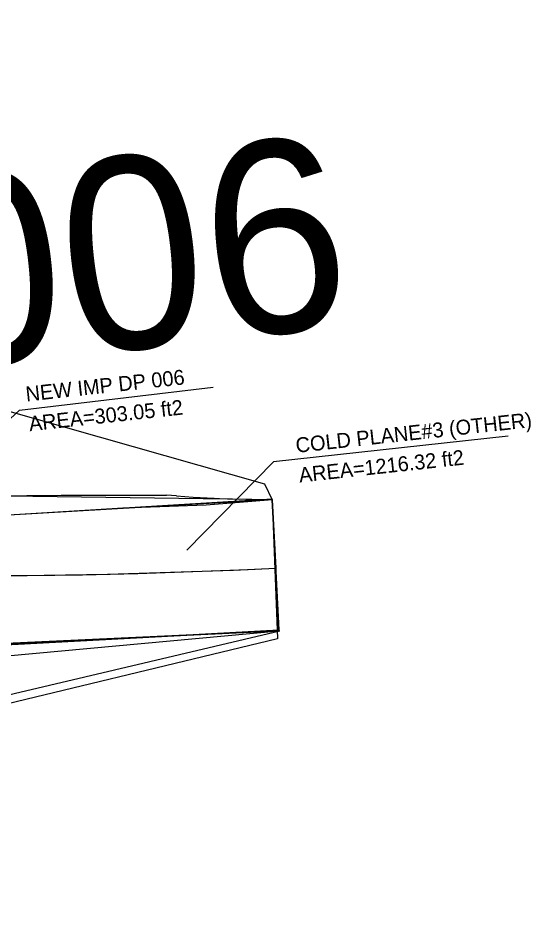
# Model space of a CAD drawing. Extents: x 1509538 to 1510847, y 401283 to 402022.
# Drawn here: x 1510636.5 to 1510732.7, y 401595.5 to 401764.5 of the extents above; entities that cross this region are included whole.
import ezdxf

# ---------------------------------------------------------------- set-up
doc = ezdxf.new("R2010")
doc.units = 0
for name, color, linetype in [('LAWE_P_T', 7, 'Continuous'), ('LDEFAULT_P', 7, 'Continuous'), ('Level 1', 7, 'Continuous'), ('Level 14', 7, 'Continuous'), ('Level 18', 7, 'Continuous'), ('Level 20', 7, 'Continuous'), ('Level 23', 7, 'Continuous'), ('Level 24', 7, 'Continuous'), ('Level 3', 7, 'Continuous'), ('PCH_P', 7, 'Continuous')]:
    doc.layers.add(name, color=color, linetype=linetype)

msp = doc.modelspace()

# ---------------------------------------------------------------- linework, layer by layer
at = {"layer": 'LAWE_P_T'}
for p, q in [((1510728.37, 401686.14), (1510684.4, 401681.34)), ((1510684.4, 401681.34), (1510668.15, 401664.81))]:
    msp.add_line(p, q, dxfattribs=at)
at = {"layer": 'LDEFAULT_P'}
msp.add_lwpolyline([(1510617.08, 401672.79), (1510636.74, 401691.05), (1510673.06, 401695.31)], dxfattribs=at)
at = {"layer": 'Level 1'}
for p, q in [((1510684.29, 401671.55), (1510684.15, 401674.32)), ((1510684.43, 401668.67), (1510684.29, 401671.55)), ((1510684.49, 401667.6), (1510684.43, 401668.67)), ((1510684.57, 401665.85), (1510684.49, 401667.6)), ((1510684.67, 401663.86), (1510684.57, 401665.85)), ((1510684.93, 401658.68), (1510684.67, 401663.86)), ((1510684.86, 401660.03), (1510684.72, 401662.82)), ((1510684.97, 401657.89), (1510684.86, 401660.03)), ((1510685.05, 401656.24), (1510684.93, 401658.68)), ((1510685.05, 401656.24), (1510684.97, 401657.89)), ((1510685.14, 401654.33), (1510685.05, 401656.24)), ((1510685.14, 401654.33), (1510685.05, 401656.24)), ((1510685.24, 401652.41), (1510685.14, 401654.33)), ((1510685.24, 401652.41), (1510685.14, 401654.33)), ((1510685.29, 401651.48), (1510685.24, 401652.41)), ((1510685.29, 401651.48), (1510685.24, 401652.41)), ((1510685.34, 401650.35), (1510685.29, 401651.48)), ((1510634.89, 401647.08), (1510685.37, 401649.83)), ((1510634.89, 401647.3), (1510685.38, 401649.66)), ((1510685.37, 401649.83), (1510685.31, 401650.97)), ((1510685.31, 401650.97), (1510685.31, 401650.97)), ((1510685.37, 401649.83), (1510685.34, 401650.35)), ((1510685.34, 401650.35), (1510685.34, 401650.35)), ((1510685.34, 401650.35), (1510685.34, 401650.35)), ((1510685.38, 401649.66), (1510685.37, 401649.83)), ((1510685.37, 401649.83), (1510685.37, 401649.83)), ((1510685.38, 401649.66), (1510685.38, 401649.66))]:
    msp.add_line(p, q, dxfattribs=at)
for points in [[(1510684.15, 401674.32), (1510634.73, 401671.34)], [(1510684.29, 401671.55), (1510684.16, 401674.23), (1510634.73, 401671.34)], [(1510684.72, 401662.82), (1510684.79, 401661.42), (1510684.29, 401671.55)], [(1510685.31, 401650.97), (1510685.29, 401651.48)]]:
    msp.add_lwpolyline(points, dxfattribs=at)
at = {"layer": 'Level 14'}
for p, q in [((1510634.7, 401674.99), (1510638.15, 401675.02)), ((1510638.15, 401675.02), (1510639.64, 401675.04)), ((1510639.64, 401675.04), (1510644.57, 401675.11)), ((1510644.57, 401675.11), (1510645.16, 401675.12)), ((1510645.16, 401675.12), (1510645.16, 401675.12)), ((1510645.16, 401675.12), (1510664.33, 401675.08)), ((1510664.33, 401675.08), (1510664.33, 401675.08)), ((1510664.33, 401675.08), (1510664.33, 401675.08)), ((1510666.22, 401674.94), (1510664.33, 401675.08)), ((1510666.22, 401674.94), (1510666.22, 401674.94)), ((1510666.22, 401674.94), (1510669.29, 401674.71)), ((1510669.29, 401674.71), (1510673.26, 401674.5)), ((1510673.26, 401674.5), (1510674.25, 401674.48)), ((1510674.25, 401674.48), (1510679.2, 401674.35)), ((1510679.2, 401674.35), (1510680.3, 401674.33)), ((1510680.3, 401674.33), (1510680.3, 401674.33)), ((1510680.3, 401674.33), (1510684.16, 401674.23)), ((1510684.16, 401674.23), (1510684.79, 401661.42))]:
    msp.add_line(p, q, dxfattribs=at)
msp.add_arc((1510626.3, 402875.58), 1215.57, 260.85794, 272.75803, dxfattribs=at)
at = {"layer": 'Level 18'}
msp.add_line((1510684.79, 401661.42), (1510684.16, 401674.23), dxfattribs=at)
for points in [[(1510671.73, 401673.2), (1510656.11, 401672.66), (1510621.58, 401670.53), (1510593.1, 401669.05), (1510570.63, 401667.06)], [(1510684.16, 401674.23), (1510680.33, 401673.91), (1510671.73, 401673.2)]]:
    msp.add_lwpolyline(points, dxfattribs=at)
msp.add_arc((1510625.43, 402859.96), 1200, 264.92169, 272.83549, dxfattribs=at)
at = {"layer": 'Level 20'}
msp.add_line((1510685.37, 401649.83), (1510684.79, 401661.42), dxfattribs=at)
msp.add_lwpolyline([(1510601.13, 401645.2), (1510622.45, 401646.41), (1510672.72, 401649.13), (1510685.37, 401649.83)], dxfattribs=at)
msp.add_arc((1510625.43, 402859.96), 1200, 264.92169, 272.83549, dxfattribs=at)
at = {"layer": 'Level 23'}
msp.add_lwpolyline([(1510410.25, 401663.98), (1510406.28, 401635.45), (1510599.09, 401629.32), (1510685.54, 401649.67), (1510635.53, 401647.32), (1510591.21, 401645.44), (1510529.65, 401648.74), (1510446.37, 401658.22)], close=True, dxfattribs=at)
at = {"layer": 'Level 24'}
msp.add_lwpolyline([(1510359.87, 401749.85), (1510436.07, 401732.12), (1510468.72, 401728.44), (1510492.07, 401724.89), (1510498.04, 401725.77), (1510520.27, 401739.91), (1510516.78, 401757.54), (1510553.49, 401764.52), (1510567.6, 401764.22), (1510578.98, 401712.86), (1510608.33, 401698.35), (1510682.71, 401677.22), (1510684.16, 401674.23), (1510685.11, 401648.19), (1510623.85, 401633.39), (1510589.3, 401615.77), (1510582.28, 401611.13), (1510485.41, 401619.76), (1510463.51, 401615.28), (1510452.26, 401619.93), (1510436.45, 401620.31), (1510422.96, 401609.85), (1510373.65, 401595.47)], dxfattribs=at)
at = {"layer": 'Level 3'}
msp.add_lwpolyline([(1510634.7, 401674.99), (1510680.3, 401674.33), (1510684.16, 401674.23), (1510684.16, 401674.23), (1510684.16, 401674.23), (1510671.73, 401673.2), (1510656.11, 401672.66), (1510621.58, 401670.53)], dxfattribs=at)
msp.add_lwpolyline([(1510601.12, 401645.2), (1510634.42, 401644.99), (1510685.38, 401649.66), (1510634.93, 401647.08)], close=True, dxfattribs=at)
at = {"layer": 'PCH_P'}
msp.add_line((1510684.16, 401674.23), (1510685.37, 401649.83), dxfattribs=at)

# ---------------------------------------------------------------- texts
at = {"layer": 'LAWE_P_T'}
for s, p in [('COLD PLANE#3 (OTHER)', (1510688.69, 401683.02)), ('AREA=1216.32 ft2', (1510689.29, 401677.45))]:
    msp.add_text(s, height=2.8, rotation=6.2219, dxfattribs=at).set_placement(p)
at = {"layer": 'LDEFAULT_P'}
for s, p in [('NEW IMP DP 006', (1510638.05, 401692.63)), ('AREA=303.05 ft2', (1510638.66, 401687.07))]:
    msp.add_text(s, height=2.8, rotation=6.2219, dxfattribs=at).set_placement(p)
at = {"layer": 'Level 3'}
msp.add_text('006', height=36, rotation=6.2215, dxfattribs=at).set_placement((1510619.9, 401698.34))

doc.saveas('drawing.dxf')
